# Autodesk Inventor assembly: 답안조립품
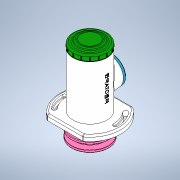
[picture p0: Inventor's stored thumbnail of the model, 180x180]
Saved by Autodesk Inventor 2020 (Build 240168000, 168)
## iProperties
Created: 2022-05
Part Number: 답안조립품
Document SubType Name: Assembly
Designer: Student
Author: Student
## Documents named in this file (21)
- C:\Users\Student\Desktop\720506V1021\답안조립품.iam
- C:\Users\Student\Desktop\720506V1021\부품.ipt
- C:\Users\Student\Desktop\720506V1021\십자볼트 M3 x 10.ipt
- C:\Users\Student\Desktop\720506V1021\와셔 3 x 6.ipt
- C:\Users\Student\Desktop\720506V1021\탑 커버.ipt
- C:\Users\Student\Desktop\720506V1021\사이드 커버.ipt
- 사이드 커버.ipt
- C:\Users\Student\Desktop\720506V1021\개스킷.ipt
- C:\Users\Student\Desktop\720506V1021\축.ipt
- C:\Users\Student\Desktop\720506V1021\V-벨트풀리.ipt
- C:\Users\Student\Desktop\720506V1021\볼트 M4 x 10.ipt
- C:\Users\Student\Desktop\720506V1021\와셔 4 x 16.ipt
- C:\Users\Student\Desktop\720506V1021\키 4 x 4.ipt
- C:\Users\Student\Desktop\720506V1021\부시1.ipt
- C:\Users\Student\Desktop\720506V1021\베어링 6202.ipt
- C:\Users\Student\Desktop\720506V1021\멈춤링 15 x 1.ipt
- C:\Users\Student\Desktop\720506V1021\멈춤링 35 x 1.6.ipt
- C:\Users\Student\Desktop\720506V1021\오일 실 15 x 30 x 7.ipt
- C:\Users\Student\Desktop\720506V1021\부시2.ipt
- C:\Users\Student\Desktop\720506V1021\와셔 10 x 21.ipt
- C:\Users\Student\Desktop\720506V1021\너트 M10.ipt
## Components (3 placed, 3 different names)
1. 개스킷:1
2. V-벨트풀리:1
3. ISO 4017 M4 x 10:1
